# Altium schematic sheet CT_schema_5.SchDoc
size 368 x 309 mm
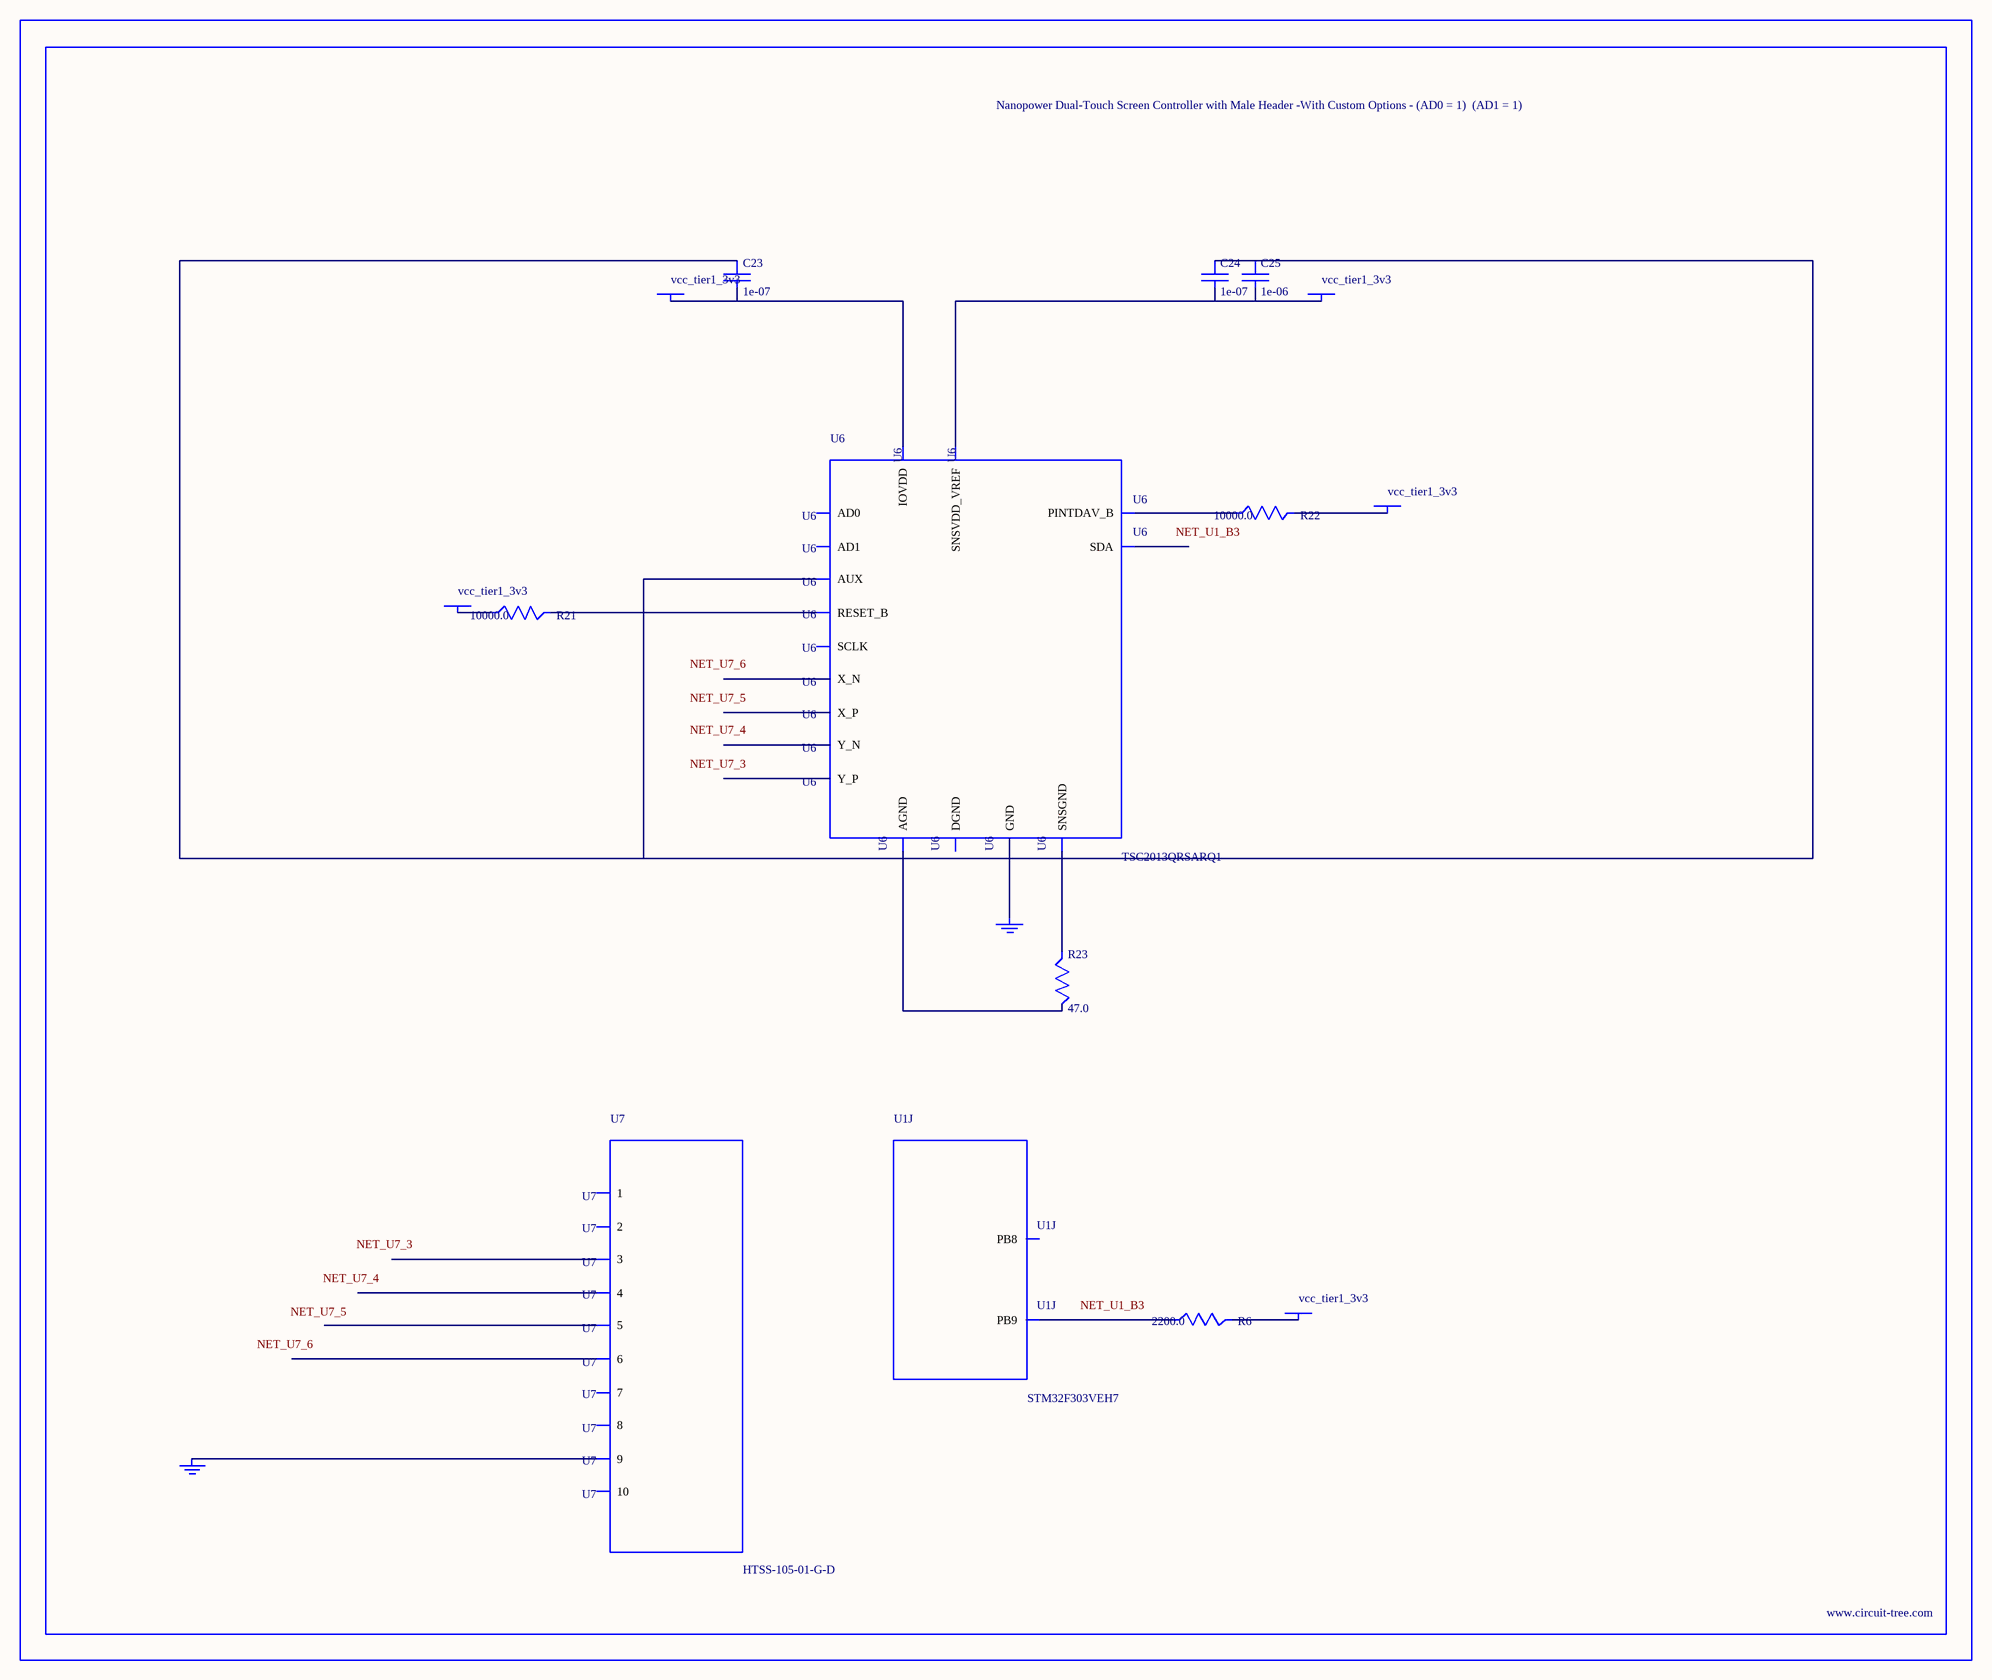
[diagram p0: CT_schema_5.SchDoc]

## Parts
BORDER4  (no value)
C23  1e-07  [C0402]
C24  1e-07  [C0402]
C25  1e-06  [C0603]
GND_INSTANCE_4_0  (no value)
GND_INSTANCE_4_1  (no value)
POWER_INSTANCE_4_0  vcc_tier1_3v3
POWER_INSTANCE_4_1  vcc_tier1_3v3
POWER_INSTANCE_4_2  vcc_tier1_3v3
POWER_INSTANCE_4_3  vcc_tier1_3v3
POWER_INSTANCE_4_4  vcc_tier1_3v3
R6  2200.0  [R0603]
R21  10000.0  [R0603]
R22  10000.0  [R0603]
R23  47.0  [R0603]
U1  STM32F303VEH7  [UFBGA100]  (part J of 10)
U6  TSC2013QRSARQ1  [QFN65P400X400X100-17N]
U7  HTSS-105-01-G-D  [HTSS-105-01-G-D]

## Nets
NetC23_1: C23.1 C24.1 C25.1 R23.1 R23.2 U6.8(AUX) U6.9(AGND) U6.15(SNSGND)
NetC23_2: C23.2 POWER_INSTANCE_4_2.0(PWR) U6.7(IOVDD)
NetC24_2: C24.2 C25.2 POWER_INSTANCE_4_3.0(PWR) U6.10(SNSVDD_VREF)
NetGND_INSTANCE_4_0_0: GND_INSTANCE_4_0.0(GND) U6.17(GND)
NetGND_INSTANCE_4_1_0: GND_INSTANCE_4_1.0(GND) U7.9
NetPOWER_INSTANCE_4_0_0: POWER_INSTANCE_4_0.0(PWR) R22.2
NetPOWER_INSTANCE_4_1_0: POWER_INSTANCE_4_1.0(PWR) R21.1
NetPOWER_INSTANCE_4_4_0: POWER_INSTANCE_4_4.0(PWR) R6.2
NetR6_1: R6.1 U1.B3(PB9)
NetR21_2: R21.2 U6.5(RESET_B)
NetR22_1: R22.1 U6.4(PINTDAV_B)

Not connected (* = marked no-connect by the designer): U1 A3(PB8); U6 1(SDA) 2(SCLK) 3(AD1) 6(DGND) 11(X_P) 12(Y_P) 13(X_N) 14(Y_N) 16(AD0); U7 1 2 3 4 5 6 7 8 10

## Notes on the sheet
- Labels drawn without touching a wire or pin: NET_U1_B3, NET_U7_3, NET_U7_4, NET_U7_5, NET_U7_6

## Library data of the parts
BORDER4 = BORDER_PAGE4
C23 C24 = C0402C104K3RACTU
C25 = C0603C105K3RACTU
GND_INSTANCE_4_0 GND_INSTANCE_4_1 = GND
POWER_INSTANCE_4_0-POWER_INSTANCE_4_4 = PWR
R6 = RC0603JR-072K2L
R21 R22 = RC0603JR-0710KL
R23 = RC0603JR-0747RL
